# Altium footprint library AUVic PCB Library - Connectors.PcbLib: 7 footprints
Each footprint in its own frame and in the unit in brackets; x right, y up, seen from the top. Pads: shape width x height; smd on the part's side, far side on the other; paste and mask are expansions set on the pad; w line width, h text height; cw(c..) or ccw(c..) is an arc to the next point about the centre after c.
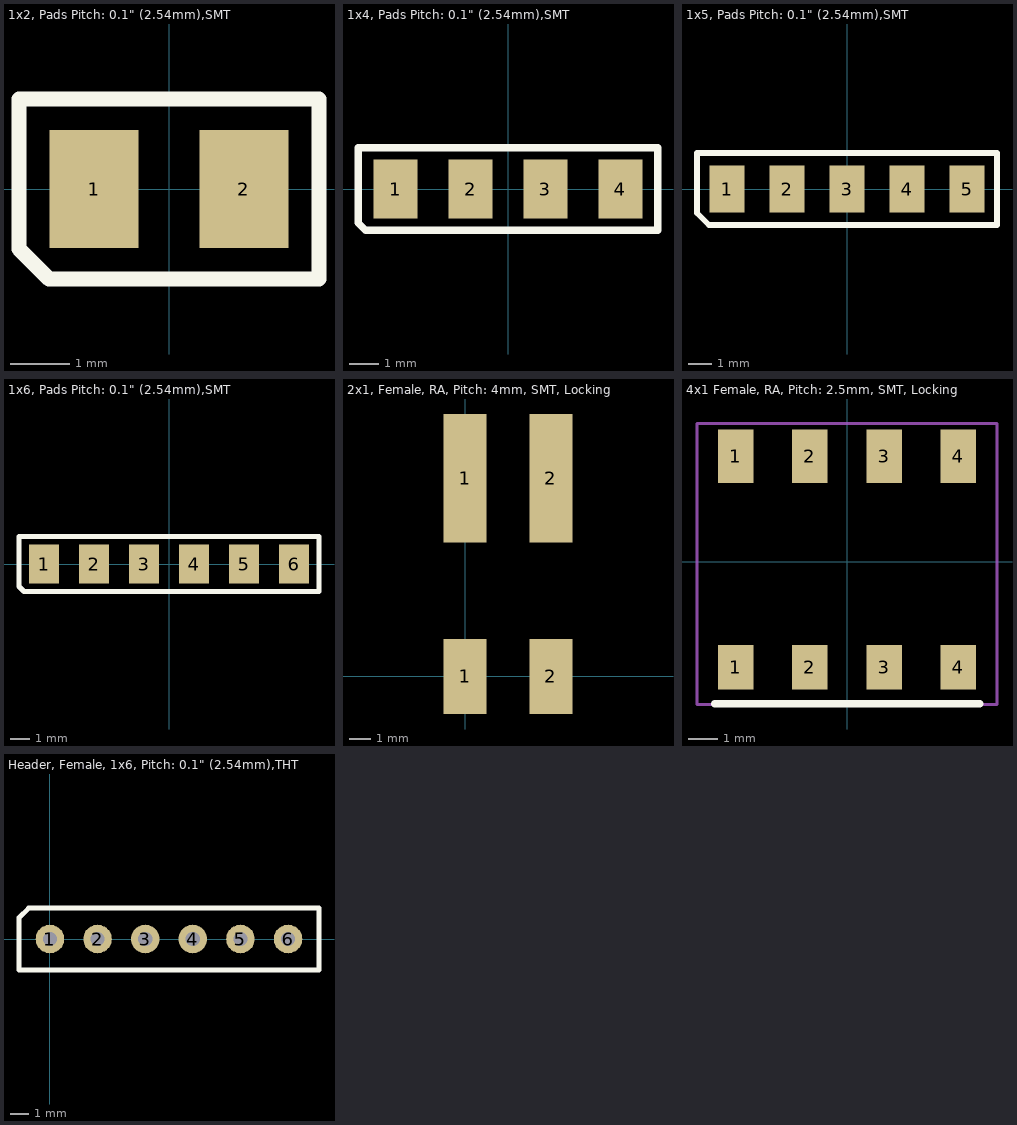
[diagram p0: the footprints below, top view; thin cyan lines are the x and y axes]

## 1x2, Pads Pitch: 0.1" (2.54mm),SMT [mm]
pads (2):
  rect 1.5x2 smd: 1(-1.27,0) 2(1.27,0)
Top Overlay:
  lines w0.254: -2.54,-1.016 -2.54,1.524 2.54,1.524 2.54,-1.524 -2.032,-1.524 -2.54,-1.016

## 1x4, Pads Pitch: 0.1" (2.54mm),SMT [mm]
pads (4):
  rect 1.5x2 smd: 1(-3.81,0) 2(-1.27,0) 3(1.27,0) 4(3.81,0)
Top Overlay:
  lines w0.254: -5.08,-1.143 -4.826,-1.397 5.08,-1.397 5.08,1.397 -5.08,1.397 -5.08,-1.143

## 1x5, Pads Pitch: 0.1" (2.54mm),SMT [mm]
pads (5):
  rect 1.5x2 smd: 1(-5.08,0) 2(-2.54,0) 3(0,0) 4(2.54,0) 5(5.08,0)
Top Overlay:
  lines w0.254: -6.35,-1.016 -5.842,-1.524 6.35,-1.524 6.35,1.524 -6.35,1.524 -6.35,-1.016

## 1x6, Pads Pitch: 0.1" (2.54mm),SMT [mm]
pads (6):
  rect 1.5x2 smd: 1(-6.35,0) 2(-3.81,0) 3(-1.27,0) 4(1.27,0) 5(3.81,0) 6(6.35,0)
Top Overlay:
  lines w0.254: -7.62,-1.143 -7.62,1.397 7.62,1.397 7.62,-1.397 -7.366,-1.397 -7.62,-1.143

## 2x1, Female, RA, Pitch: 4mm, SMT, Locking [mm]
pads (4):
  rect 2x3.5 smd: 1(0,0) 2(4,0)
  rect 2x6 smd: 1(0,9.25) 2(4,9.25)
3D body: height 4.25, standoff 0, extent -1.95,-1.25 5.95,11.75

## 4x1 Female, RA, Pitch: 2.5mm, SMT, Locking [mm]
pads (8):
  rect 1.2x1.5 smd: 1(-3.75,-3.55) 2(-1.25,-3.55) 3(1.25,-3.55) 4(3.75,-3.55)
  rect 1.2x1.8 smd: 1(-3.75,3.55) 2(-1.25,3.55) 3(1.25,3.55) 4(3.75,3.55)
Top Overlay:
  lines w0.254: -4.45,-4.775 4.475,-4.775
Mechanical 1:
  lines w0.1: -5.05,-4.8 -5.05,4.65 5.05,4.65 5.05,-4.8 -5.05,-4.8
3D body: height 5, standoff 0, extent -5,-4.75 5,4.25

## Header, Female, 1x6, Pitch: 0.1" (2.54mm),THT [mil]
pads (6):
  round 60 hole 30: 1(0,0) 2(100,0) 3(200,0) 4(300,0) 5(400,0) 6(500,0)
Top Overlay:
  lines w10: -65,-65 -65,45 -45,65 565,65 565,-65 -65,-65
3D body: height 128, standoff -112, extent -49.99,-49.99 550.01,50.01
